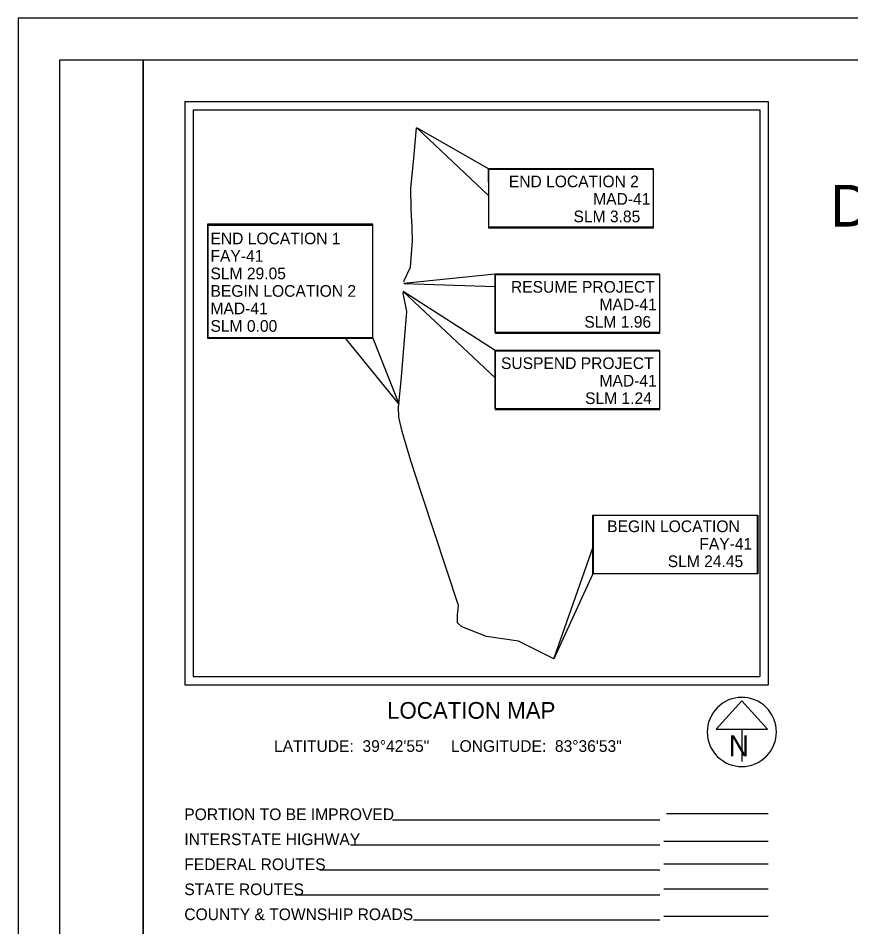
# Model space of a CAD drawing. Extents: x 0 to 34, y 0 to 22.
# Drawn here: x 0 to 9.99, y 11.1 to 22 of the extents above; entities that cross this region are included whole.
import ezdxf

# ---------------------------------------------------------------- set-up
doc = ezdxf.new("R2010")
doc.units = 0
for name, color, linetype in [('SH_Border', 7, 'Continuous'), ('SH_Cut_Line', 7, 'Continuous'), ('SH_Data', 7, 'Continuous'), ('SH_Text', 7, 'Continuous')]:
    doc.layers.add(name, color=color, linetype=linetype)

msp = doc.modelspace()

# ---------------------------------------------------------------- linework, layer by layer
at = {"layer": 'SH_Border'}
for points in [[(0.5, 21.5), (1.5, 21.5), (1.5, 0.5), (0.5, 0.5)], [(1.5, 21.5), (33.5, 21.5), (33.5, 0.5), (1.5, 0.5)]]:
    msp.add_lwpolyline(points, close=True, dxfattribs=at)
at = {"layer": 'SH_Cut_Line'}
msp.add_lwpolyline([(0, 0), (34, 0), (34, 22), (0, 22)], close=True, dxfattribs=at)
at = {"layer": 'SH_Data'}
for p, q in [((2, 21), (9, 21)), ((2, 21), (2, 14)), ((9, 21), (9, 14)), ((2.1, 20.9), (2.1, 14.1)), ((2.1, 20.9), (8.9, 20.9)), ((8.9, 20.9), (8.9, 14.1)), ((2.1, 14.1), (8.9, 14.1)), ((2.1, 14.1), (2.1, 14.1)), ((2, 14), (9, 14)), ((8.685, 13.809), (8.377, 13.468)), ((8.992, 13.468), (8.685, 13.809)), ((8.377, 13.468), (8.992, 13.468)), ((8.685, 13.468), (8.685, 13.081)), ((8.685, 13.435), (8.685, 13.435)), ((8.685, 13.435), (8.685, 13.435)), ((7.783, 12.455), (9, 12.455)), ((7.7, 12.377), (4.494, 12.377)), ((9, 12.121), (7.75, 12.121)), ((7.7, 12.077), (3.99, 12.077)), ((7.7, 11.777), (3.619, 11.777)), ((9, 11.849), (7.75, 11.849)), ((7.7, 11.477), (3.329, 11.477)), ((9, 11.549), (7.75, 11.549)), ((7.7, 11.177), (4.745, 11.177)), ((9, 11.222), (7.75, 11.222))]:
    msp.add_line(p, q, dxfattribs=at)
for points in [[(4.63, 18.842), (4.631, 18.852), (4.708, 19.013), (4.733, 19.33), (4.729, 19.489), (4.716, 19.708), (4.714, 19.962), (4.746, 20.275), (4.779, 20.686)], [(6.429, 14.313), (6.003, 14.523), (5.622, 14.579), (5.325, 14.695), (5.274, 14.743), (5.274, 14.841), (5.283, 14.953), (4.847, 16.271), (4.713, 16.688), (4.608, 17.042), (4.57, 17.211), (4.566, 17.333), (4.596, 17.65), (4.666, 18.479), (4.621, 18.699), (4.621, 18.709)]]:
    msp.add_lwpolyline(points, dxfattribs=at)
for points in [[(5.646, 20.193), (4.786, 20.686), (5.65, 19.867)], [(5.646, 19.486), (7.627, 19.486), (7.627, 20.193), (5.646, 20.193)], [(4.255, 19.528), (2.274, 19.528), (2.274, 18.161), (4.255, 18.161)], [(5.723, 18.928), (4.629, 18.818), (5.723, 18.781)], [(5.723, 18.221), (7.703, 18.221), (7.703, 18.928), (5.723, 18.928)], [(5.723, 18.012), (4.622, 18.72), (5.726, 17.686)], [(4.255, 18.161), (4.57, 17.374), (3.93, 18.161)], [(5.723, 17.305), (7.703, 17.305), (7.703, 18.012), (5.723, 18.012)], [(6.897, 16.038), (8.877, 16.038), (8.877, 15.332), (6.897, 15.332)], [(6.897, 15.332), (6.429, 14.313), (6.901, 15.658)]]:
    msp.add_lwpolyline(points, close=True, dxfattribs=at)
msp.add_arc((8.685, 13.435), 0.415, 129.7798, 129.7633, dxfattribs=at)
at = {"layer": 'SH_Text'}
for points in [[(7.621, 19.492), (5.65, 19.492), (5.65, 20.189), (7.621, 20.189)], [(2.28, 19.517), (4.251, 19.517), (4.251, 18.165), (2.28, 18.165)], [(7.697, 18.227), (5.726, 18.227), (5.726, 18.924), (7.697, 18.924)], [(7.697, 17.311), (5.726, 17.311), (5.726, 18.008), (7.697, 18.008)], [(8.872, 16.032), (6.901, 16.032), (6.901, 15.336), (8.872, 15.336)]]:
    msp.add_lwpolyline(points, close=True, dxfattribs=at)

# ---------------------------------------------------------------- texts
at = {"layer": 'SH_Data'}
for s, height, p in [('END LOCATION 2', 0.14, (5.889, 19.971)), ('MAD-41', 0.14, (6.901, 19.761)), ('SLM 3.85', 0.14, (6.665, 19.551)), ('END LOCATION 1', 0.14, (2.308, 19.287)), ('FAY-41', 0.14, (2.308, 19.077)), ('SLM 29.05', 0.14, (2.308, 18.867)), ('BEGIN LOCATION 2', 0.14, (2.308, 18.657)), ('RESUME PROJECT', 0.14, (5.914, 18.706)), ('MAD-41', 0.14, (2.308, 18.447)), ('MAD-41', 0.14, (6.977, 18.496)), ('SLM 1.96', 0.14, (6.795, 18.286)), ('SLM 0.00', 0.14, (2.308, 18.237)), ('SUSPEND PROJECT', 0.14, (5.795, 17.79)), ('MAD-41', 0.14, (6.977, 17.58)), ('SLM 1.24', 0.14, (6.804, 17.37)), ('BEGIN LOCATION ', 0.14, (7.069, 15.833)), ('FAY-41', 0.14, (8.175, 15.623)), ('SLM 24.45', 0.14, (7.796, 15.413)), ('N', 0.25, (8.529, 13.144))]:
    msp.add_text(s, height=height, dxfattribs=at).set_placement(p)
at = {"layer": 'SH_Text'}
for s, height, p in [('DEPARTMENT OF TRANSPORTATION', 0.5, (9.747, 19.5)), ('LOCATION MAP', 0.2, (4.427, 13.594)), ('LATITUDE:  39°42\'55"     LONGITUDE:  83°36\'53"', 0.14, (3.071, 13.196)), ('PORTION TO BE IMPROVED', 0.14, (1.994, 12.377)), ('INTERSTATE HIGHWAY', 0.14, (1.994, 12.077)), ('FEDERAL ROUTES', 0.14, (1.994, 11.777)), ('STATE ROUTES', 0.14, (1.994, 11.477)), ('COUNTY & TOWNSHIP ROADS', 0.14, (1.994, 11.177))]:
    msp.add_text(s, height=height, dxfattribs=at).set_placement(p)

doc.saveas('drawing.dxf')
